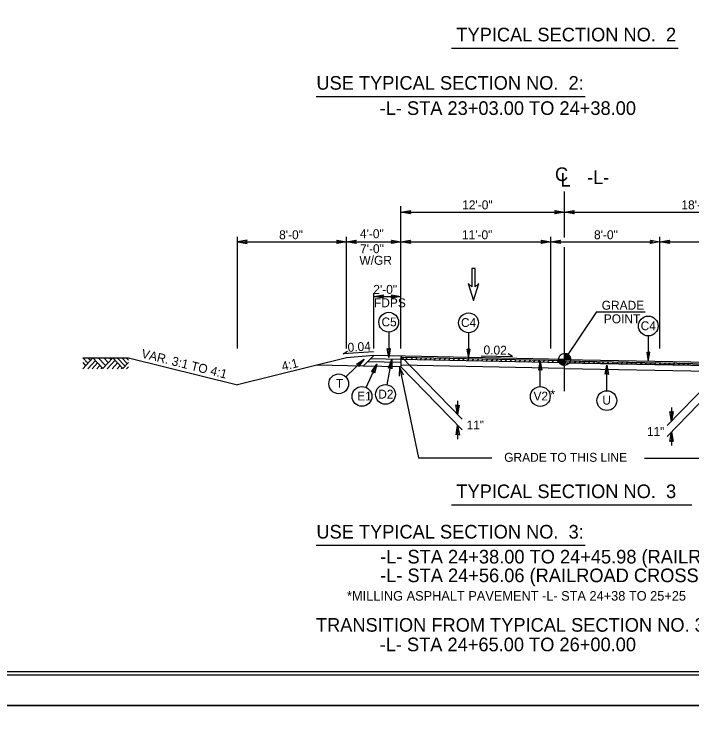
# Model space of a CAD drawing. Extents: x 1901718 to 1902220, y 193828 to 194187.
# Drawn here: x 1902010.3 to 1902060, y 193936.9 to 193988.8 of the extents above; entities that cross this region are included whole.
import ezdxf

# ---------------------------------------------------------------- set-up
doc = ezdxf.new("R2010")
doc.units = 0
for name, color, linetype in [('Old_Level_1', 7, 'Continuous'), ('Old_Level_11', 7, 'Continuous'), ('Old_Level_2', 7, 'Continuous'), ('Old_Level_20', 7, 'Continuous'), ('Old_Level_3', 7, 'Continuous'), ('Prop Dimension', 7, 'Continuous'), ('Prop Dimension Text', 7, 'Continuous'), ('Sheet Border Standard 30in CELL', 7, 'Continuous'), ('Sheet Cutting Line CELL', 7, 'Continuous'), ('Sheet Plot Border Inside CELL', 7, 'Continuous'), ('Sheet Plot Border Outside CELL', 7, 'Continuous'), ('Typical Terminator CELL', 7, 'Continuous')]:
    doc.layers.add(name, color=color, linetype=linetype)

# ---------------------------------------------------------------- blocks, each defined once
blk = doc.blocks.new('TERMINATOR')
at = {"layer": 'Typical Terminator CELL'}
blk.add_lwpolyline([(-0.469, 0.081), (0, 0), (-0.471, -0.083), (-0.411, 0)], close=True, dxfattribs=at)

msp = doc.modelspace()

# ---------------------------------------------------------------- linework, layer by layer
at = {"layer": 'Old_Level_1'}
for p, q in [((1902050.692, 193972.371), (1902050.692, 193975.746)), ((1902049.692, 193964.218), (1902049.692, 193972.416)), ((1902050.692, 193961.101), (1902050.692, 193971.672)), ((1902034.445, 193963.836), (1902034.77, 193964.018)), ((1902036.68, 193963.982), (1902034.445, 193963.836)), ((1902036.692, 193963.706), (1902034.692, 193963.546)), ((1902036.692, 193963.706), (1902035.916, 193962.93)), ((1902050.692, 193963.426), (1902036.692, 193963.706)), ((1902038.692, 193963.666), (1902043.169, 193959.042)), ((1902038.692, 193963.562), (1902038.692, 193962.874)), ((1902050.692, 193963.322), (1902038.692, 193963.562)), ((1902038.692, 193963.422), (1902038.83, 193963.559)), ((1902044.575, 193963.691), (1902046.879, 193963.643)), ((1902046.879, 193963.643), (1902046.556, 193963.829)), ((1902050.692, 193963.426), (1902050.692, 193963.867)), ((1902015.35, 193963.546), (1902015.725, 193963.143)), ((1902015.35, 193962.741), (1902016.092, 193963.538)), ((1902015.35, 193963.184), (1902015.556, 193962.962)), ((1902015.724, 193962.741), (1902016.278, 193963.337)), ((1902015.725, 193963.546), (1902015.912, 193963.345)), ((1902016.033, 193962.741), (1902016.434, 193963.17)), ((1902016.092, 193963.538), (1902016.816, 193962.759)), ((1902016.483, 193963.546), (1902017.016, 193962.973)), ((1902016.816, 193962.759), (1902017.547, 193963.545)), ((1902016.881, 193963.546), (1902017.214, 193963.187)), ((1902017.126, 193962.741), (1902017.712, 193963.369)), ((1902017.283, 193963.546), (1902017.416, 193963.403)), ((1902017.496, 193962.741), (1902017.896, 193963.17)), ((1902017.547, 193963.545), (1902018.288, 193962.749)), ((1902017.869, 193963.546), (1902018.449, 193962.923)), ((1902018.202, 193963.546), (1902018.616, 193963.102)), ((1902018.288, 193962.749), (1902018.692, 193963.184)), ((1902018.522, 193963.546), (1902018.692, 193963.363)), ((1902018.692, 193963.546), (1902026.692, 193961.546)), ((1902034.692, 193963.546), (1902026.692, 193961.546)), ((1902038.692, 193963.208), (1902036.243, 193963.257)), ((1902038.692, 193963.416), (1902036.447, 193963.461)), ((1902050.692, 193963.176), (1902038.692, 193963.416)), ((1902039.034, 193963.409), (1902039.177, 193963.552)), ((1902039.38, 193963.402), (1902039.524, 193963.546)), ((1902039.727, 193963.395), (1902039.87, 193963.539)), ((1902040.074, 193963.389), (1902040.217, 193963.532)), ((1902040.42, 193963.382), (1902040.563, 193963.525)), ((1902040.767, 193963.375), (1902040.91, 193963.518)), ((1902041.113, 193963.368), (1902041.257, 193963.511)), ((1902041.46, 193963.361), (1902041.603, 193963.504)), ((1902041.807, 193963.354), (1902041.95, 193963.497)), ((1902042.153, 193963.347), (1902042.297, 193963.49)), ((1902042.156, 193963.347), (1902042.299, 193963.49)), ((1902042.502, 193963.34), (1902042.645, 193963.483)), ((1902042.849, 193963.333), (1902042.992, 193963.476)), ((1902043.195, 193963.326), (1902043.339, 193963.469)), ((1902043.542, 193963.319), (1902043.685, 193963.462)), ((1902043.889, 193963.312), (1902044.032, 193963.455)), ((1902044.235, 193963.305), (1902044.378, 193963.448)), ((1902044.582, 193963.298), (1902044.725, 193963.442)), ((1902044.929, 193963.291), (1902045.072, 193963.435)), ((1902045.275, 193963.284), (1902045.418, 193963.428)), ((1902045.622, 193963.278), (1902045.765, 193963.421)), ((1902045.968, 193963.271), (1902046.112, 193963.414)), ((1902046.306, 193963.264), (1902046.449, 193963.407)), ((1902046.315, 193963.264), (1902046.458, 193963.407)), ((1902046.653, 193963.257), (1902046.796, 193963.4)), ((1902046.999, 193963.25), (1902047.143, 193963.393)), ((1902047.346, 193963.243), (1902047.489, 193963.386)), ((1902047.693, 193963.236), (1902047.836, 193963.379)), ((1902048.039, 193963.229), (1902048.182, 193963.372)), ((1902048.386, 193963.222), (1902048.529, 193963.365)), ((1902048.733, 193963.215), (1902048.876, 193963.358)), ((1902049.079, 193963.208), (1902049.222, 193963.352)), ((1902049.426, 193963.201), (1902049.569, 193963.345)), ((1902049.772, 193963.195), (1902049.916, 193963.338)), ((1902050.119, 193963.188), (1902050.262, 193963.331)), ((1902050.251, 193963.426), (1902050.692, 193963.426)), ((1902050.466, 193963.181), (1902050.609, 193963.324)), ((1902050.691, 193962.985), (1902050.692, 193963.426)), ((1902050.692, 193963.426), (1902050.691, 193962.985)), ((1902050.692, 193963.426), (1902070.692, 193963.026)), ((1902051.133, 193963.426), (1902050.692, 193963.426)), ((1902050.692, 193963.322), (1902062.692, 193963.082)), ((1902050.692, 193963.182), (1902050.83, 193963.319)), ((1902050.692, 193963.176), (1902062.692, 193962.936)), ((1902062.692, 193962.936), (1902050.692, 193963.176)), ((1902051.034, 193963.169), (1902051.177, 193963.312)), ((1902051.38, 193963.162), (1902051.524, 193963.306)), ((1902051.727, 193963.155), (1902051.87, 193963.299)), ((1902052.074, 193963.149), (1902052.217, 193963.292)), ((1902052.42, 193963.142), (1902052.563, 193963.285)), ((1902052.767, 193963.135), (1902052.91, 193963.278)), ((1902053.113, 193963.128), (1902053.257, 193963.271)), ((1902053.46, 193963.121), (1902053.603, 193963.264)), ((1902053.807, 193963.114), (1902053.95, 193963.257)), ((1902054.153, 193963.107), (1902054.297, 193963.25)), ((1902054.156, 193963.107), (1902054.299, 193963.25)), ((1902054.502, 193963.1), (1902054.645, 193963.243)), ((1902054.849, 193963.093), (1902054.992, 193963.236)), ((1902055.195, 193963.086), (1902055.339, 193963.229)), ((1902055.542, 193963.079), (1902055.685, 193963.222)), ((1902055.889, 193963.072), (1902056.032, 193963.215)), ((1902056.235, 193963.065), (1902056.378, 193963.208)), ((1902056.582, 193963.058), (1902056.725, 193963.202)), ((1902056.929, 193963.051), (1902057.072, 193963.195)), ((1902057.275, 193963.044), (1902057.418, 193963.188)), ((1902057.622, 193963.038), (1902057.765, 193963.181)), ((1902057.968, 193963.031), (1902058.112, 193963.174)), ((1902062.692, 193963.186), (1902058.216, 193958.562)), ((1902058.306, 193963.024), (1902058.449, 193963.167)), ((1902058.315, 193963.024), (1902058.458, 193963.167)), ((1902058.653, 193963.017), (1902058.796, 193963.16)), ((1902058.999, 193963.01), (1902059.143, 193963.153)), ((1902059.346, 193963.003), (1902059.489, 193963.146)), ((1902059.693, 193962.996), (1902059.836, 193963.139)), ((1902016.38, 193962.741), (1902016.607, 193962.984)), ((1902016.691, 193962.741), (1902016.762, 193962.817)), ((1902017.862, 193962.741), (1902018.079, 193962.974)), ((1902018.157, 193962.741), (1902018.226, 193962.815)), ((1902018.558, 193962.741), (1902018.692, 193962.884)), ((1902035.916, 193962.93), (1902032.501, 193962.998)), ((1902038.692, 193962.874), (1902035.916, 193962.93)), ((1902050.692, 193962.76), (1902038.692, 193963)), ((1902038.692, 193962.874), (1902043.169, 193958.25)), ((1902050.692, 193962.76), (1902062.692, 193962.52)), ((1902062.692, 193962.394), (1902058.216, 193957.77)), ((1902042.85, 193960.371), (1902042.85, 193959.371)), ((1902058.535, 193959.891), (1902058.535, 193958.891)), ((1902042.85, 193958.579), (1902042.85, 193957.579)), ((1902058.535, 193958.099), (1902058.535, 193957.099))]:
    msp.add_line(p, q, dxfattribs=at)
for points in [[(1902050.696, 193963.867), (1902050.696, 193963.867), (1902050.696, 193963.426)], [(1902050.705, 193963.867), (1902050.705, 193963.426)], [(1902050.714, 193963.866), (1902050.714, 193963.426)], [(1902050.723, 193963.866), (1902050.723, 193963.426)], [(1902050.732, 193963.865), (1902050.732, 193963.426)], [(1902050.74, 193963.864), (1902050.74, 193963.426)], [(1902050.749, 193963.863), (1902050.749, 193963.426)], [(1902050.758, 193963.862), (1902050.758, 193963.426)], [(1902050.767, 193963.861), (1902050.767, 193963.426)], [(1902050.776, 193963.859), (1902050.776, 193963.426)], [(1902050.785, 193963.857), (1902050.785, 193963.426)], [(1902050.793, 193963.855), (1902050.793, 193963.426)], [(1902050.802, 193963.853), (1902050.802, 193963.426)], [(1902050.811, 193963.851), (1902050.811, 193963.426)], [(1902050.82, 193963.849), (1902050.82, 193963.426)], [(1902050.829, 193963.846), (1902050.829, 193963.426)], [(1902050.837, 193963.843), (1902050.837, 193963.426)], [(1902050.846, 193963.84), (1902050.846, 193963.426)], [(1902050.855, 193963.836), (1902050.855, 193963.426)], [(1902050.864, 193963.832), (1902050.864, 193963.426)], [(1902050.873, 193963.828), (1902050.873, 193963.426)], [(1902050.882, 193963.824), (1902050.882, 193963.426)], [(1902050.89, 193963.82), (1902050.89, 193963.426)], [(1902050.899, 193963.815), (1902050.899, 193963.426)], [(1902050.908, 193963.81), (1902050.908, 193963.426)], [(1902050.917, 193963.805), (1902050.917, 193963.426)], [(1902050.926, 193963.801), (1902050.926, 193963.426)], [(1902050.934, 193963.795), (1902050.934, 193963.426)], [(1902050.943, 193963.789), (1902050.943, 193963.426)], [(1902050.952, 193963.782), (1902050.952, 193963.426)], [(1902050.961, 193963.776), (1902050.961, 193963.426)], [(1902050.97, 193963.769), (1902050.97, 193963.426)], [(1902050.979, 193963.761), (1902050.979, 193963.426)], [(1902050.987, 193963.753), (1902050.987, 193963.426)], [(1902050.996, 193963.746), (1902050.996, 193963.426)], [(1902051.005, 193963.737), (1902051.005, 193963.426)], [(1902051.014, 193963.728), (1902051.014, 193963.426)], [(1902051.023, 193963.718), (1902051.023, 193963.426)], [(1902051.032, 193963.707), (1902051.032, 193963.426)], [(1902051.04, 193963.697), (1902051.04, 193963.426)], [(1902051.049, 193963.685), (1902051.049, 193963.426)], [(1902051.058, 193963.672), (1902051.058, 193963.426)], [(1902051.067, 193963.658), (1902051.067, 193963.426)], [(1902051.076, 193963.644), (1902051.076, 193963.426)], [(1902051.084, 193963.628), (1902051.084, 193963.426)], [(1902051.093, 193963.609), (1902051.093, 193963.426)], [(1902051.102, 193963.589), (1902051.102, 193963.426)], [(1902051.111, 193963.564), (1902051.111, 193963.426)], [(1902015.35, 193963.546), (1902018.692, 193963.546)], [(1902050.253, 193963.426), (1902050.253, 193963.378)], [(1902050.262, 193963.426), (1902050.262, 193963.326)], [(1902050.271, 193963.426), (1902050.271, 193963.295)], [(1902050.28, 193963.426), (1902050.28, 193963.268)], [(1902050.289, 193963.426), (1902050.289, 193963.248)], [(1902050.297, 193963.426), (1902050.297, 193963.229)], [(1902050.306, 193963.426), (1902050.306, 193963.213)], [(1902050.315, 193963.426), (1902050.315, 193963.197)], [(1902050.324, 193963.426), (1902050.324, 193963.183)], [(1902050.333, 193963.426), (1902050.333, 193963.17)], [(1902050.342, 193963.426), (1902050.342, 193963.159)], [(1902050.35, 193963.426), (1902050.35, 193963.148)], [(1902050.359, 193963.426), (1902050.359, 193963.137)], [(1902050.368, 193963.426), (1902050.368, 193963.127)], [(1902050.377, 193963.426), (1902050.377, 193963.117)], [(1902050.386, 193963.426), (1902050.386, 193963.109)], [(1902050.395, 193963.426), (1902050.395, 193963.101)], [(1902050.403, 193963.426), (1902050.403, 193963.093)], [(1902050.412, 193963.426), (1902050.412, 193963.085)], [(1902050.421, 193963.426), (1902050.421, 193963.078)], [(1902050.43, 193963.426), (1902050.43, 193963.071)], [(1902050.439, 193963.426), (1902050.439, 193963.066)], [(1902050.447, 193963.426), (1902050.447, 193963.06)], [(1902050.456, 193963.426), (1902050.456, 193963.054)], [(1902050.465, 193963.426), (1902050.465, 193963.048)], [(1902050.474, 193963.426), (1902050.474, 193963.043)], [(1902050.483, 193963.426), (1902050.483, 193963.038)], [(1902050.492, 193963.426), (1902050.492, 193963.033)], [(1902050.5, 193963.426), (1902050.5, 193963.029)], [(1902050.509, 193963.426), (1902050.509, 193963.025)], [(1902050.518, 193963.426), (1902050.518, 193963.021)], [(1902050.527, 193963.426), (1902050.527, 193963.018)], [(1902050.536, 193963.426), (1902050.536, 193963.014)], [(1902050.544, 193963.426), (1902050.544, 193963.011)], [(1902050.553, 193963.426), (1902050.553, 193963.008)], [(1902050.562, 193963.426), (1902050.562, 193963.005)], [(1902050.571, 193963.426), (1902050.571, 193963.003)], [(1902050.58, 193963.426), (1902050.58, 193963)], [(1902050.589, 193963.426), (1902050.589, 193962.998)], [(1902050.597, 193963.426), (1902050.597, 193962.996)], [(1902050.606, 193963.426), (1902050.606, 193962.994)], [(1902050.615, 193963.426), (1902050.615, 193962.992)], [(1902050.624, 193963.426), (1902050.624, 193962.991)], [(1902050.633, 193963.426), (1902050.633, 193962.989)], [(1902050.641, 193963.426), (1902050.641, 193962.988)], [(1902050.65, 193963.426), (1902050.65, 193962.987)], [(1902050.659, 193963.426), (1902050.659, 193962.986)], [(1902050.668, 193963.426), (1902050.668, 193962.986)], [(1902050.677, 193963.426), (1902050.677, 193962.985)], [(1902050.686, 193963.426), (1902050.686, 193962.985), (1902050.686, 193962.985)], [(1902051.12, 193963.534), (1902051.12, 193963.426)], [(1902051.129, 193963.489), (1902051.129, 193963.426)], [(1902038.873, 193962.268), (1902038.579, 193962.877), (1902038.552, 193962.201)], [(1902038.579, 193962.877), (1902039.974, 193956.209), (1902045.365, 193956.209)], [(1902063.24, 193962.383), (1902061.937, 193956.153), (1902056.546, 193956.153)]]:
    msp.add_lwpolyline(points, dxfattribs=at)
msp.add_circle((1902050.692, 193963.426), 0.441, dxfattribs=at)
for start, end in [(359.9905, 89.9905), (179.9905, 269.9905)]:
    msp.add_arc((1902050.692, 193963.426), 0.441, start, end, dxfattribs=at)
at = {"layer": 'Old_Level_11'}
for p, q in [((1902042.4, 193986.273), (1902059.026, 193986.273)), ((1902032.462, 193982.726), (1902052.205, 193982.726)), ((1902037.794, 193965.429), (1902037.794, 193963.555)), ((1902043.647, 193965.383), (1902043.647, 193963.509)), ((1902056.834, 193965.15), (1902056.834, 193963.276)), ((1902034.644, 193962.14), (1902035.981, 193963.453)), ((1902036.133, 193961.37), (1902036.916, 193963.073)), ((1902037.684, 193961.565), (1902038.021, 193963.408)), ((1902048.913, 193961.425), (1902048.913, 193963.3)), ((1902053.796, 193961.125), (1902053.796, 193963)), ((1902042.4, 193952.748), (1902059.026, 193952.748)), ((1902043.4, 193952.748), (1902060.026, 193952.748)), ((1902032.462, 193949.781), (1902052.205, 193949.781))]:
    msp.add_line(p, q, dxfattribs=at)
for points in [[(1902037.909, 193964.226), (1902037.794, 193963.555), (1902037.674, 193964.23), (1902037.794, 193964.144)], [(1902043.531, 193964.18), (1902043.647, 193963.509), (1902043.766, 193964.184), (1902043.647, 193964.098)], [(1902056.718, 193963.947), (1902056.834, 193963.276), (1902056.953, 193963.951), (1902056.834, 193963.865)], [(1902035.421, 193963.065), (1902035.981, 193963.453), (1902035.583, 193962.894), (1902035.561, 193963.04)], [(1902036.531, 193962.511), (1902036.916, 193963.073), (1902036.743, 193962.41), (1902036.67, 193962.537)], [(1902037.787, 193962.769), (1902038.021, 193963.408), (1902038.017, 193962.723), (1902037.915, 193962.829)], [(1902048.797, 193962.628), (1902048.913, 193963.3), (1902049.032, 193962.624), (1902048.913, 193962.71)], [(1902053.68, 193962.328), (1902053.796, 193963), (1902053.915, 193962.324), (1902053.796, 193962.41)]]:
    msp.add_lwpolyline(points, close=True, dxfattribs=at)
for centre in [(1902037.794, 193966.154), (1902043.647, 193966.108), (1902056.834, 193965.875), (1902034.126, 193961.632), (1902037.554, 193960.852), (1902035.83, 193960.711), (1902048.913, 193960.7), (1902053.796, 193960.4)]:
    msp.add_circle(centre, 0.725, dxfattribs=at)
at = {"layer": 'Old_Level_3'}
for q in [(1902050.692, 193963.426), (1902056.607, 193966.911)]:
    msp.add_line((1902053.044, 193966.911), q, dxfattribs=at)
at = {"layer": 'Prop Dimension'}
for p, q in [((1902038.692, 193964.218), (1902038.692, 193974.669)), ((1902038.692, 193974.24), (1902054.692, 193974.24)), ((1902050.692, 193974.24), (1902068.692, 193974.24)), ((1902026.692, 193964.218), (1902026.692, 193972.416)), ((1902034.692, 193964.218), (1902034.692, 193972.416)), ((1902049.692, 193964.218), (1902049.692, 193972.416)), ((1902057.692, 193964.218), (1902057.692, 193972.416)), ((1902038.692, 193972.046), (1902049.692, 193972.046)), ((1902049.692, 193972.046), (1902057.192, 193972.046)), ((1902057.692, 193972.046), (1902068.692, 193972.046)), ((1902036.692, 193964.218), (1902036.692, 193968.296)), ((1902036.692, 193968.046), (1902038.692, 193968.046))]:
    msp.add_line(p, q, dxfattribs=at)
msp.add_lwpolyline([(1902044.405, 193969.006), (1902044.134, 193968.756), (1902044.134, 193970.089), (1902043.884, 193970.089), (1902043.884, 193968.756), (1902043.614, 193969.006), (1902044.009, 193967.735)], close=True, dxfattribs=at)
msp.add_lwpolyline([(1902044.405, 193969.006), (1902044.134, 193968.756), (1902044.134, 193970.089), (1902043.884, 193970.089), (1902043.884, 193968.756), (1902043.614, 193969.006), (1902044.009, 193967.735)], close=True, dxfattribs=at)
at = {"layer": 'Prop Dimension Text'}
for p, q in [((1902026.692, 193972.046), (1902034.692, 193972.046)), ((1902034.692, 193972.046), (1902038.692, 193972.046))]:
    msp.add_line(p, q, dxfattribs=at)
at = {"layer": 'Sheet Border Standard 30in CELL'}
msp.add_lwpolyline([(1902132.544, 194045.514), (1901982.544, 194045.514), (1901982.544, 193940.514), (1902132.544, 193940.514)], close=True, dxfattribs=at)
at = {"layer": 'Sheet Cutting Line CELL'}
for p, q in [((1901965.844, 193938.014), (1902134.244, 193938.014)), ((1902134.244, 193938.014), (1901965.844, 193938.014))]:
    msp.add_line(p, q, dxfattribs=at)
at = {"layer": 'Sheet Plot Border Inside CELL'}
msp.add_lwpolyline([(1902133.794, 194045.769), (1901967.144, 194045.769), (1901967.144, 193940.259), (1902133.794, 193940.259)], close=True, dxfattribs=at)
at = {"layer": 'Sheet Plot Border Outside CELL'}
for points in [[(1902134.244, 194048.014), (1901965.844, 194048.014), (1901965.844, 193938.014), (1902134.244, 193938.014)], [(1902134.244, 193938.014), (1901965.844, 193938.014), (1901965.844, 193828.014), (1902134.244, 193828.014)]]:
    msp.add_lwpolyline(points, close=True, dxfattribs=at)

# ---------------------------------------------------------------- block references
at = {"layer": 'Old_Level_1', "xscale": 1.5, "yscale": 1.5}
for p, rotation in [((1902042.85, 193959.371), -90), ((1902058.535, 193958.891), -90), ((1902042.85, 193958.579), 90), ((1902058.535, 193958.099), 90)]:
    msp.add_blockref('TERMINATOR', p, dxfattribs=dict(at, rotation=rotation))
at = {"layer": 'Prop Dimension', "xscale": 1.5, "rotation": 180}
for p, yscale in [((1902038.692, 193974.24), 1.5), ((1902050.692, 193974.24), 1.5), ((1902026.692, 193972.046), -1.5), ((1902034.692, 193972.046), 1.5), ((1902038.692, 193972.046), 1.5), ((1902049.692, 193972.046), 1.5), ((1902057.692, 193972.046), 1.5), ((1902036.692, 193968.046), 1.5)]:
    msp.add_blockref('TERMINATOR', p, dxfattribs=dict(at, yscale=yscale))
at = {"layer": 'Prop Dimension', "xscale": 1.5, "yscale": 1.5}
for p in [(1902050.692, 193974.24), (1902034.692, 193972.046), (1902038.692, 193972.046), (1902049.692, 193972.046), (1902057.692, 193972.046), (1902038.692, 193968.046)]:
    msp.add_blockref('TERMINATOR', p, dxfattribs=at)

# ---------------------------------------------------------------- texts
at = {"layer": 'Old_Level_1'}
for s, rotation, p in [('VAR. 3:1 TO 4:1', 345.9638, (1902019.595, 193963.568)), ('4:1', 14.0362, (1902030.025, 193962.576))]:
    msp.add_text(s, height=0.656, rotation=rotation, dxfattribs=at).set_placement(p)
for s, height, p in [('11"', 0.6491, (1902043.509, 193958.288)), ('11"', 0.6491, (1902056.74, 193957.808)), ('GRADE TO THIS LINE', 0.656, (1902046.264, 193955.907))]:
    msp.add_text(s, height=height, dxfattribs=at).set_placement(p)
at = {"layer": 'Old_Level_11'}
for s, p in [('TYPICAL SECTION NO.  2', (1902042.756, 193986.767)), ('USE TYPICAL SECTION NO.  2:', (1902032.486, 193983.22)), ('-L- STA 23+03.00 TO 24+38.00', (1902037.126, 193981.369)), ('TYPICAL SECTION NO.  3', (1902042.756, 193953.242)), ('USE TYPICAL SECTION NO.  3:', (1902032.486, 193950.275)), ('-L- STA 24+38.00 TO 24+45.98 (RAILROAD CROSSING)', (1902037.162, 193948.443)), ('-L- STA 24+56.06 (RAILROAD CROSSING) TO 24+65.00', (1902037.162, 193947.073)), ('TRANSITION FROM TYPICAL SECTION NO. 3 TO TYPICAL SECTION NO. 1', (1902032.45, 193943.436)), ('-L- STA 24+65.00 TO 26+00.00', (1902037.126, 193942.002))]:
    msp.add_text(s, height=1, dxfattribs=at).set_placement(p)
at = {"layer": 'Old_Level_2'}
msp.add_text('C', height=1, dxfattribs=at).set_placement((1902049.991, 193976.516))
for s, height, rotation, p in [('L', 1, 359.9469, (1902050.393, 193976.112)), ('-L-', 1, 359.9469, (1902052.341, 193976.295)), ('0.04', 0.656, 3.7166, (1902034.795, 193963.971)), ('0.02', 0.656, 358.8084, (1902044.741, 193963.799))]:
    msp.add_text(s, height=height, rotation=rotation, dxfattribs=at).set_placement(p)
at = {"layer": 'Old_Level_20'}
for s, height, p in [('C5', 0.6491, (1902037.265, 193965.848)), ('C4', 0.6491, (1902043.093, 193965.802)), ('C4', 0.6491, (1902056.28, 193965.569)), ('E1', 0.6491, (1902035.485, 193960.407)), ('D2', 0.6491, (1902037.027, 193960.548)), ('V2', 0.6491, (1902048.417, 193960.407)), ('U', 0.649, (1902053.468, 193960.107))]:
    msp.add_text(s, height=height, dxfattribs=at).set_placement(p)
msp.add_text('T', height=0.649, rotation=360, dxfattribs=at).set_placement((1902033.919, 193961.341))
at = {"layer": 'Old_Level_3'}
for s, p in [('GRADE', (1902053.416, 193967.069)), ('POINT', (1902053.574, 193966.075))]:
    msp.add_text(s, height=0.656, dxfattribs=at).set_placement(p)
at = {"layer": 'Prop Dimension'}
for s, p in [('12\'-0" ', (1902043.18, 193974.438)), ('18\'-0" ', (1902059.265, 193974.438)), ('11\'-0" ', (1902043.162, 193972.244)), ('8\'-0" ', (1902052.854, 193972.244))]:
    msp.add_text(s, height=0.656, dxfattribs=at).set_placement(p)
for s, p in [('2\'-0"', (1902036.66, 193968.235)), ('FDPS', (1902036.708, 193967.251))]:
    msp.add_text(s, height=0.656, rotation=360, dxfattribs=at).set_placement(p)
at = {"layer": 'Prop Dimension Text'}
for s, p in [('8\'-0"', (1902029.75, 193972.244)), ('4\'-0"', (1902035.679, 193972.321)), ('7\'-0"', (1902035.688, 193971.221)), ('W/GR', (1902035.641, 193970.368))]:
    msp.add_text(s, height=0.656, dxfattribs=at).set_placement(p)
for s, p in [('*', (1902049.64, 193960.51)), ('*MILLING ASPHALT PAVEMENT -L- STA 24+38 TO 25+25', (1902034.734, 193945.718))]:
    msp.add_text(s, height=0.7, rotation=360, dxfattribs=at).set_placement(p)

doc.saveas('drawing.dxf')
